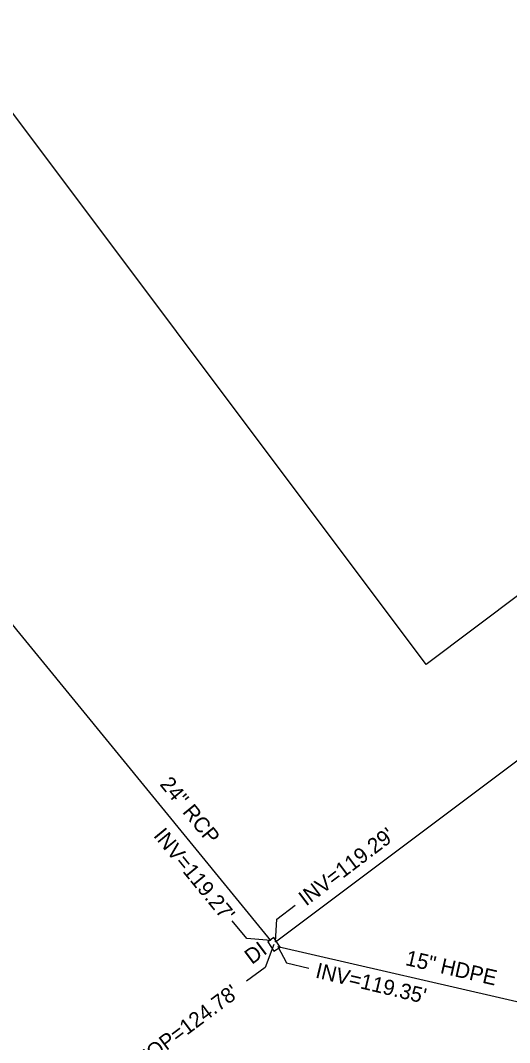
# Model space of a CAD drawing. Extents: x 2186615 to 2188822, y 629899 to 631820.
# Drawn here: x 2188055 to 2188182.7, y 631223.1 to 631489.6 of the extents above; entities that cross this region are included whole.
import ezdxf

# ---------------------------------------------------------------- set-up
doc = ezdxf.new("R2010")
doc.units = 0
for name, color, linetype in [('Exist Building', 7, 'Continuous'), ('Exist Structure Minor Drop Inlet', 7, 'Continuous'), ('Exist Structure Minor Drop Inlet Leader', 7, 'Continuous'), ('Exist Structure Minor Drop Inlet Text', 7, 'Continuous'), ('Exist Structure Minor Drop Inlet Top Elevation', 7, 'Continuous'), ('Exist Structure Minor Pipes HDPE 15 Inch', 7, 'Continuous'), ('Exist Structure Minor Pipes HDPE 15 Inch Invert', 7, 'Continuous'), ('Exist Structure Minor Pipes HDPE 15 Inch Leader', 7, 'Continuous'), ('Exist Structure Minor Pipes HDPE 15 Inch Text', 7, 'Continuous'), ('Exist Structure Minor Pipes RCP 24 Inch', 7, 'Continuous'), ('Exist Structure Minor Pipes RCP 24 Inch Invert', 7, 'Continuous'), ('Exist Structure Minor Pipes RCP 24 Inch Leader', 7, 'Continuous'), ('Exist Structure Minor Pipes RCP 24 Inch Text', 7, 'Continuous')]:
    doc.layers.add(name, color=color, linetype=linetype)

msp = doc.modelspace()

# ---------------------------------------------------------------- linework, layer by layer
at = {"layer": 'Exist Building'}
msp.add_lwpolyline([(2188166.77, 631732.88), (2188362.11, 631472.67), (2188160.94, 631321.65), (2187965.6, 631581.87)], close=True, dxfattribs=at)
at = {"layer": 'Exist Structure Minor Drop Inlet'}
msp.add_lwpolyline([(2188119.56, 631249.35), (2188121.18, 631246.9), (2188122.8, 631247.98), (2188121.17, 631250.44), (2188119.56, 631249.35)], dxfattribs=at)
at = {"layer": 'Exist Structure Minor Drop Inlet Leader'}
msp.add_lwpolyline([(2188121.15, 631248.67), (2188118.87, 631242.68), (2188114.07, 631239.07)], dxfattribs=at)
at = {"layer": 'Exist Structure Minor Pipes HDPE 15 Inch'}
msp.add_line((2188122.19, 631248.08), (2188206.55, 631228.73), dxfattribs=at)
at = {"layer": 'Exist Structure Minor Pipes HDPE 15 Inch Leader'}
msp.add_lwpolyline([(2188122.19, 631248.08), (2188124.5, 631243.88), (2188130.33, 631242.48)], dxfattribs=at)
at = {"layer": 'Exist Structure Minor Pipes RCP 24 Inch'}
for p, q in [((2188121.59, 631249.35), (2188427.77, 631478.57)), ((2188120.41, 631249.66), (2188024.37, 631366.93))]:
    msp.add_line(p, q, dxfattribs=at)
at = {"layer": 'Exist Structure Minor Pipes RCP 24 Inch Leader'}
for points in [[(2188121.59, 631249.35), (2188121.98, 631255.28), (2188126.77, 631258.89)], [(2188120.41, 631249.66), (2188114.14, 631250.2), (2188110.33, 631254.83)]]:
    msp.add_lwpolyline(points, dxfattribs=at)

# ---------------------------------------------------------------- texts
at = {"layer": 'Exist Structure Minor Drop Inlet Text'}
msp.add_text('DI', height=4, rotation=36.8593, dxfattribs=at).set_placement((2188115.44, 631243.29))
at = {"layer": 'Exist Structure Minor Drop Inlet Top Elevation'}
msp.add_text("TOP=124.78'", height=4, rotation=36.8891, dxfattribs=at).set_placement((2188087.17, 631216.38))
at = {"layer": 'Exist Structure Minor Pipes HDPE 15 Inch Invert'}
msp.add_text("INV=119.35'", height=4, rotation=346.4645, dxfattribs=at).set_placement((2188131.81, 631240.06))
at = {"layer": 'Exist Structure Minor Pipes HDPE 15 Inch Text'}
msp.add_text('15" HDPE', height=4, rotation=347.0804, dxfattribs=at).set_placement((2188155.29, 631243.31))
at = {"layer": 'Exist Structure Minor Pipes RCP 24 Inch Invert'}
for s, rotation, p in [("INV=119.27'", 309.381, (2188089.57, 631276.97)), ("INV=119.29'", 37.0894, (2188129.57, 631258.51))]:
    msp.add_text(s, height=4, rotation=rotation, dxfattribs=at).set_placement(p)
at = {"layer": 'Exist Structure Minor Pipes RCP 24 Inch Text'}
msp.add_text('24" RCP', height=4, rotation=309.3164, dxfattribs=at).set_placement((2188091.21, 631290.36))

doc.saveas('drawing.dxf')
